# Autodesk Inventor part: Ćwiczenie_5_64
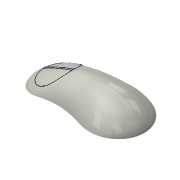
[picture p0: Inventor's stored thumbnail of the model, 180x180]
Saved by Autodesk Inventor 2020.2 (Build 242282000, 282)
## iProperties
Created: 2005-06
Part Number: Ćwiczenie_5_64
Document SubType Name: Modeling
Designer: F.Stasiak
Manufacturer: Standard
Standards Organization: Custom
Density: 1 g/cm^3
Material: Ogólny
Appearance: Gładkie — w kolorze kości słoniowej
Manager: www.cadconsulting.pl
Company: Fabian Stasiak CAD Consulting
Author: F.Stasiak
Subject: Zbiór ćwiczeń. Autodesk Inventor 2020. Kurs podstawowy
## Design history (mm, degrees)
sketch "Szkic 3D1"
sketch "Szkic 3D2"
sketch "Szkic 3D3"
sketch "Szkic 3D4"
node "Punkt konstrukcyjny1"
node "Punkt konstrukcyjny2"
sketch "Szkic2"
  geometry: L1 (54.182, 1.4)-(54.182, 13.585); L2 (-60.025, 19.509)-(-60.025, 1.232); A1 r 1.917 centre (52.265, 7.492) between (52.841, 5.664) and (52.841, 9.32); A2 r 6.154 centre (-53.87, 10.37) between (-57.308, 15.475) and (-57.308, 5.266); 7 further points
  constraints: 4 end point, 4 midpoint, 4 vertical, 2 centre point, 2 point on circle, 14 other
  dimensions: "d2" = 5 dimension on L1.start L1.end; "d3" = 7.5 dimension on L2.start L2.end
node "Płaszczyzna konstrukcyjna1"
sketch "Szkic3"
  geometry: A1 r 29.381 centre (25.333, -14.883) between (50.666, 0) and (0, 0); 1 further point
  constraints: 3 point on circle, 1 centre point
node "Płaszczyzna konstrukcyjna2"
sketch "Szkic4"
  geometry: A1 r 32.191 centre (29.616, -12.614) between (59.233, 0) and (0, 0); 1 further point
  constraints: 3 point on circle, 1 centre point, 1 other
sketch "Szkic 3D8"
sketch "Szkic 3D9" dims "d4" = 10 (derived), "d5" = 10 (derived)
sketch "Szkic 3D10" dims "d6" = 10 (derived), "d7" = 10 (derived)
feature "PowWyciągnięciaZłożonego1" dims "d8" = 0, "d9" = 90 deg, "d10" = 0, "d11" = 90 deg, "d12" = 0, "d13" = 90 deg, "d14" = 0, "d15" = 90 deg, "d16" = 0, "d17" = 90 deg
feature "PowWyciągnięciaZłożonego2" dims "d18" = 0, "d19" = 90 deg, "d20" = 20, "d21" = 90 deg, "d22" = 0, "d23" = 90 deg
  node "Krawędzie1"
feature "PowWyciągnięciaZłożonego3" dims "d24" = 20, "d25" = 90 deg, "d26" = 0, "d27" = 90 deg, "d28" = 0, "d29" = 90 deg
  node "Krawędzie2"
feature "Zszyj powierzchnię1" dims "d42" = 0.254 (derived)
feature "Powierzchnia1"
sketch "Szkic5"
  geometry: 4 further points
  constraints: 2 vertical alignment, 1 other
feature "PowWyciągnięciaProstego1" sketch "Szkic5" dims "d30" = 21.25, "d31" = 0
feature "Podział1"
feature "Usuń powierzchnię1"
feature "Zszyj powierzchnię2" dims "d43" = 0.254 (derived)
node "Płaszczyzna konstrukcyjna3"
sketch "Szkic6"
  geometry: L1 (-44.981, 1)-(-15.019, 1); L2 (-44.981, -1)-(-15.019, -1); L3 (0, 0)-(-30, 0); 2 other entities
  constraints: 6 end point, 4 horizontal, 1 parallel, 9 other
  dimensions: "d36" = 2 distance between parallel lines of L2 L1
feature "PowWyciągnięciaProstego2" dims "d37" = 40, "d38" = 0
feature "PowWyciągnięciaProstego3" dims "d39" = 40, "d40" = 0
sketch "Szkic 3D11"
  node "Przecięcie 3D1"
  node "Przecięcie 3D2"
  node "Przecięcie 3D3"
  node "Przecięcie 3D4"
node "Płaszczyzna pod bitmapę"
node "Bryła1"
node "Korpusy bryłowe"
node "Korpusy powierzchniowe"
body "Srf1"
body "Srf2"
body "Srf3"
body "Srf4"
node "Odniesienie1"
body "Srf6"
body "Srf7"
body "Srf8"
body "Srf5"
other parameters: "d33" = 15
